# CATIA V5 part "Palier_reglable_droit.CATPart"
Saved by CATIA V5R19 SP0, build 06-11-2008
Part number: Palier_reglable_droit
Bounding box of the stored display mesh (mm): x 0 to 100, y 0 to 212, z -8 to 76
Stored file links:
  G:\EU_thinkMotion\CFAO_2010\MMS_groupe1\MMS_groupe1\OK\vduret\vduret\CATIA\Palier_reglable_droit.CATPart
  F:\CFAO TP\Machine_de_coupe.CATProduct
  G:\EU_thinkMotion\CFAO_2010\MMS_groupe1\MMS_groupe1\OK\vduret\vduret\CATIA\Axe_outil_g.CATPart
  G:\EU_thinkMotion\CFAO_2010\MMS_groupe1\MMS_groupe1\OK\vduret\vduret\CATIA\Bras_d.CATPart
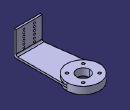
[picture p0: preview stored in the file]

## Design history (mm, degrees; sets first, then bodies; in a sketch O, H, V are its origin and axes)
External parameters (linked from other documents)
  External.Hauteur_bras = 200 mm
Body1 (main body)
  Sketch1 on yz-plane, origin (0, 0, 0), H (0, 1, 0), V (0, 0, 1)
    line L1 (0, 76) -> (0, 0)
    line L2 (0, 0) -> (212, 0)
    line L3 (212, 0) -> (212, 6)
    line L4 (212, 6) -> (6, 6)
    line L5 (6, 6) -> (6, 76)
    line L6 (6, 76) -> (0, 76)
    reference intersected line E1 through (0, 0) direction (0, 1) from zx-plane
    length L5 = 70
    length L3 = 6
    length L6 = 6
    length L2 = 212 {= External.Hauteur_bras +12mm}
    vertical: L1 V, L3 V, L5 V
    horizontal: L2 H, L4 H, L6 H
    coincidence: L2 H, E1 L1
  Pad1: profile Sketch1, direction (1, 0, 0), length 100
  Sketch2 on face of Pad1 from Sketch1.L4, origin (0, 0, 6), H (1, 0, 0), V (0, 1, 0)
    circle A1 centre (50, 162) radius 25
    point P1 (50, 162)
    reference projected line E1 (0, 250) -> (0, 6) from edge [start face of Pad1 | face of Pad1 from Sketch1.L4]
    reference projected line E2 (0, 0) -> (70, 0) from edge [face of Pad1 from Sketch1.L2 | face of Pad1 from Sketch1.L1]
    radius A1 = 25
    distance E1 P1 = 50
    distance E2 P1 = 162 {= External.Hauteur_bras -38mm}
  Pocket1: profile Sketch2, direction (0, 0, -1), through (limit type 6)
  Sketch3 on face of Pad1 from Sketch1.L5, origin (0, 6, 0), H (-1, 0, 0), V (0, 0, 1)
    construction line L1 (-60, 100) -> (-60, -40)
    reference projected line E1 (-100, 6) -> (-100, 76) from edge [face of Pad1 from Sketch1.L5 | end face of Pad1]
    construction line L2 (-120, 41) -> (60, 41)
    reference projected line E2 (0, 76) -> (-100, 76) from edge [face of Pad1 from Sketch1.L6 | face of Pad1 from Sketch1.L5]
    circle A1 centre (-76, 46) radius 3
    point P5 (-76, 46)
    point P6 (-76, 56)
    circle A2 centre (-76, 56) radius 3
    point P7 (-76, 66)
    circle A3 centre (-76, 66) radius 3
    axis line L3 (-76, 17.2716) -> (-76, 107.2716)
    reference projected line E3 (0, 76) -> (-100, 76) from edge [face of Pad1 from Sketch1.L6 | face of Pad1 from Sketch1.L5]
    circle A4 centre (-76, 16) radius 3
    circle A5 centre (-76, 26) radius 3
    circle A6 centre (-76, 36) radius 3
    circle A7 centre (-44, 66) radius 3
    circle A8 centre (-44, 56) radius 3
    circle A9 centre (-44, 46) radius 3
    circle A10 centre (-44, 36) radius 3
    circle A11 centre (-44, 26) radius 3
    circle A12 centre (-44, 16) radius 3
    distance L1 E1 = 40
    distance L2 E2 = 35
    radius A1 = 3
    distance P5 L1 = 16
    distance P7 P6 = 10
    distance P6 P5 = 10
    distance P7 E3 = 10
    radius A3 = 3
    radius A2 = 3
    vertical: L1 V, L3 V
    horizontal: L2 H
    coincidence: P5 L3, P6 L3, P7 L3
    symmetry: A3 A4 L2, A2 A5 L2, A1 A6 L2, A3 A7 L1, A2 A8 L1, A1 A9 L1, A6 A10 L1, A5 A11 L1, A4 A12 L1
  Pocket2: profile Sketch3, direction (0, -1, 0), through (limit type 6)
  Fillet1: radius 50, on edge [face of Pad1 from Sketch1.L3 | end face of Pad1]; edge [start face of Pad1 | face of Pad1 from Sketch1.L3]
  Sketch4 on face of Pad1 from Sketch1.L2, origin (0, 0, 0), H (1, 0, 0), V (0, -1, 0)
    circle A1 centre (50, -162) radius 50
    point P1 (50, -162)
    reference projected arc E1 centre (50, -162) radius 50 from (50, -212) to (100, -162) ccw from edge [face of Pad1 from Sketch1.L2 | face of Fillet1]
    circle A2 centre (50, -162) radius 20
    circle A3 centre (25, -187) radius 4
    point P2 (25, -187)
    construction line L1 (-10.7972, -162) -> (119.2028, -162)
    axis line L2 (50, -110) -> (50, -220)
    circle A4 centre (75, -187) radius 4
    circle A5 centre (25, -137) radius 4
    circle A6 centre (75, -137) radius 4
    radius A2 = 20
    radius A3 = 4
    distance P2 L2 = 25
    distance P2 L1 = 25
    coincidence: A1 E1, L1 P1, L2 P1
    horizontal: L1 H
    vertical: L2 V
    symmetry: A3 A4 L2, A3 A5 L1, A4 A6 L1
  Pad2: profile Sketch4, direction (0, 0, -1), length 8, opposite side length 14
  Sketch5 on face of Pad1 from Sketch1.L2, origin (0, 0, 0), H (1, 0, 0), V (0, -1, 0)
    line L1 (20, 0) -> (20, -6)
    line L2 (20, -6) -> (0, -158.7404)
    line L3 (0, -158.7404) -> (0, 0)
    line L4 (0, 0) -> (20, 0)
    reference projected circle E1 centre (50, -162) radius 50 from edge [face of Pad2 from Sketch4.A1 | end face of Pad2]
    length L1 = 6
    length L4 = 20
    vertical: L1 V, L3 V
    horizontal: L4 H
    tangency: L2 E1
  Pocket3: profile Sketch5, direction (0, 0, 1), through (limit type 6)
  Fillet2: radius 5, on edge [face of Pad1 from Sketch1.L5 | face of Pad1 from Sketch1.L4]
  Fillet3: radius 5, on edge [face of Pad1 from Sketch1.L2 | face of Pad1 from Sketch1.L1]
